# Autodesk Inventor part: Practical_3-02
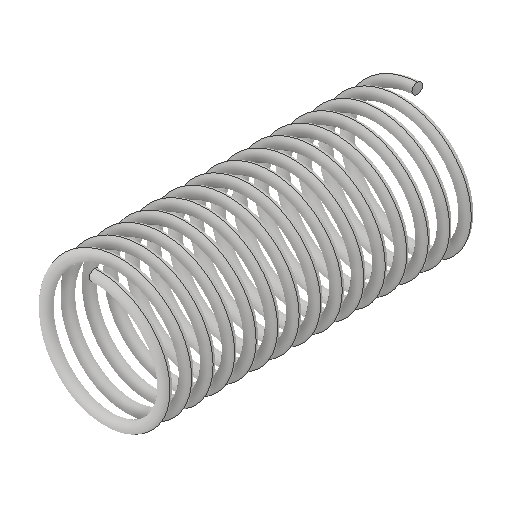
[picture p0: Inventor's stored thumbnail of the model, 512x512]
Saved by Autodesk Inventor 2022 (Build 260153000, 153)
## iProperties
Created: 2016-02
Part Number: Practical_3-02
Material: Generic
Document SubType Name: Modeling
Designer: Gaurav
Density: 1 g/cm^3
Appearance: Default
Author: Gaurav
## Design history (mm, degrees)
sketch "Sketch1"
  geometry: L1 (0, 0)-(0, -150); C1 r 2.5 at (30, 0)
  constraints: 2 end point, 1 centre point, 1 vertical
  dimensions: "d0" = 150 distance of L1.start L1.end; "d1" = 5 diameter of C1; "d2" = 30 distance of C1.centre L1.start
coil "Coil3" sketch "Sketch1" pitch "d19" = 10; turns "d21" = 10; dims "d20" = 150, "d22" = 0, angle "d23" = 90 deg, angle "d24" = 90 deg, "d25" = 0, "d26" = 0
body "Solid3"
